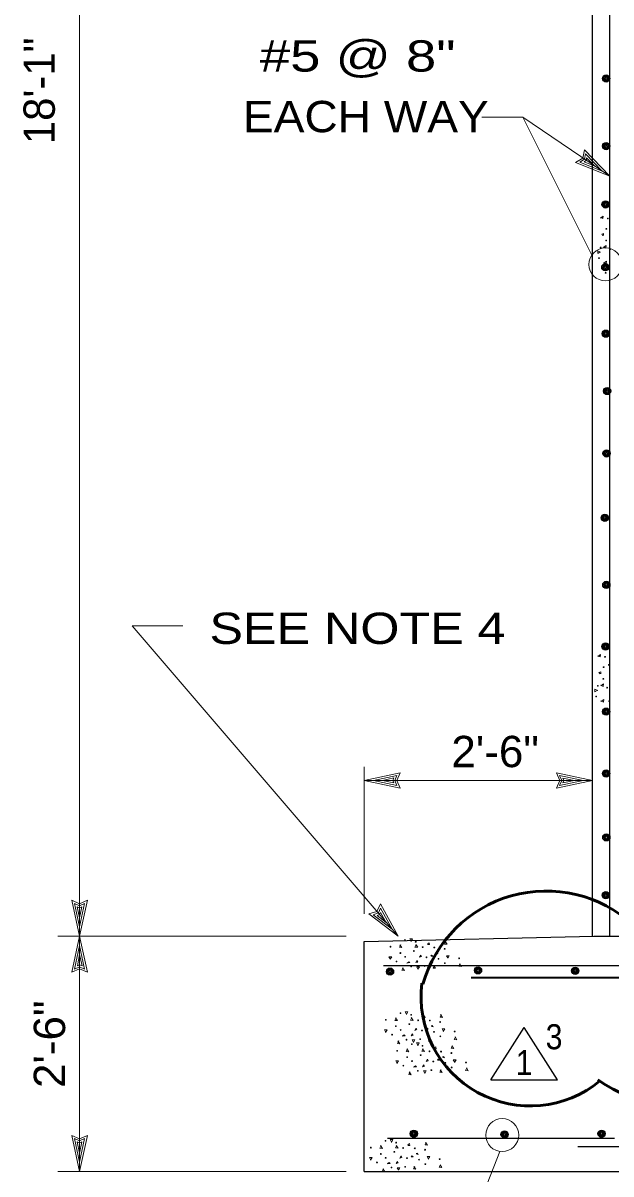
# Model space of a CAD drawing. Extents: x -28.1 to 13.9, y -16.1 to 13.9.
# Drawn here: x -11.031 to -8.685, y 2.985 to 7.58 of the extents above; entities that cross this region are included whole.
import ezdxf
from ezdxf.enums import TextEntityAlignment as Align

# ---------------------------------------------------------------- set-up
doc = ezdxf.new("R2010")
doc.units = 0
doc.header["$LTSCALE"] = 0.05
doc.layers.add('1', color=7, linetype='Continuous', lineweight=13)
doc.layers.add('2', color=7, linetype='Continuous', lineweight=13)

msp = doc.modelspace()

# ---------------------------------------------------------------- linework, layer by layer
at = {"layer": '1'}
for p, q in [((-10.80504, 3.93369), (-10.80504, 10.50069)), ((-9.03704, 7.20369), (-8.76104, 6.65269)), ((-8.80904, 7.02469), (-8.79004, 7.03569)), ((-8.79204, 7.02569), (-8.78304, 7.03169)), ((-8.68904, 6.96769), (-8.79104, 7.07369)), ((-8.79004, 7.03569), (-8.78604, 7.05769)), ((-8.72004, 6.98869), (-8.78604, 7.05769)), ((-8.78304, 7.03169), (-8.78204, 7.04169)), ((-8.74904, 7.00869), (-8.78204, 7.04169)), ((-8.68904, 6.96769), (-8.82604, 7.02269)), ((-8.72004, 6.98869), (-8.80904, 7.02469)), ((-8.74904, 7.00869), (-8.79204, 7.02569)), ((-9.67004, 4.02269), (-9.67004, 4.60969)), ((-9.67004, 4.55569), (-9.52604, 4.58669)), ((-9.67004, 4.55569), (-8.75904, 4.55569)), ((-9.67004, 4.55569), (-9.52604, 4.52469)), ((-9.63304, 4.55569), (-9.53904, 4.57569)), ((-9.63304, 4.55569), (-9.53904, 4.53569)), ((-9.59704, 4.55569), (-9.55204, 4.56569)), ((-9.59704, 4.55569), (-9.55204, 4.54669)), ((-9.55204, 4.56569), (-9.55604, 4.55569)), ((-9.55604, 4.55569), (-9.55204, 4.54669)), ((-9.53904, 4.57569), (-9.54804, 4.55569)), ((-9.54804, 4.55569), (-9.53904, 4.53569)), ((-8.75904, 4.55569), (-8.90304, 4.58669)), ((-8.75904, 4.55569), (-8.90304, 4.52469)), ((-8.79604, 4.55569), (-8.89004, 4.57569)), ((-8.88104, 4.55569), (-8.89004, 4.57569)), ((-8.79604, 4.55569), (-8.89004, 4.53569)), ((-8.89004, 4.53569), (-8.88104, 4.55569)), ((-8.83204, 4.55569), (-8.87704, 4.56469)), ((-8.87304, 4.55569), (-8.87704, 4.56469)), ((-8.83204, 4.55569), (-8.87704, 4.54569)), ((-8.87704, 4.54569), (-8.87304, 4.55569)), ((-10.80504, 3.93369), (-10.83604, 4.07769)), ((-10.80504, 3.97069), (-10.82504, 4.06469)), ((-10.82504, 4.06469), (-10.80504, 4.05569)), ((-10.80504, 4.00669), (-10.81504, 4.05169)), ((-10.81504, 4.05169), (-10.80504, 4.04769)), ((-10.80504, 3.93369), (-10.77404, 4.07769)), ((-10.80504, 3.97069), (-10.78504, 4.06469)), ((-10.80504, 4.05569), (-10.78504, 4.06469)), ((-10.80504, 4.00669), (-10.79604, 4.05169)), ((-10.80504, 4.04769), (-10.79604, 4.05169)), ((-9.61304, 4.02669), (-9.60404, 4.04569)), ((-9.53404, 3.93369), (-9.60404, 4.06369)), ((-9.55804, 3.96169), (-9.60404, 4.04569)), ((-9.53404, 3.93369), (-9.65104, 4.02269)), ((-9.63404, 4.01969), (-9.61304, 4.02669)), ((-9.55804, 3.96169), (-9.63404, 4.01969)), ((-9.61804, 4.01669), (-9.60804, 4.02069)), ((-9.58204, 3.98869), (-9.61804, 4.01669)), ((-9.60804, 4.02069), (-9.60404, 4.02869)), ((-9.58204, 3.98869), (-9.60404, 4.02869)), ((-9.74204, 3.93369), (-10.89204, 3.93369)), ((-10.80504, 3.93369), (-10.83604, 3.78969)), ((-10.80504, 2.99469), (-10.80504, 3.93369)), ((-10.80504, 3.93369), (-10.77404, 3.78969)), ((-10.80504, 3.89669), (-10.82504, 3.80269)), ((-10.80504, 3.86069), (-10.81404, 3.81569)), ((-10.80504, 3.89669), (-10.78504, 3.80269)), ((-10.80504, 3.86069), (-10.79504, 3.81569)), ((-10.80504, 3.81969), (-10.81404, 3.81569)), ((-10.79504, 3.81569), (-10.80504, 3.81969)), ((-10.80504, 3.81169), (-10.82504, 3.80269)), ((-10.78504, 3.80269), (-10.80504, 3.81169)), ((-10.80504, 2.99469), (-10.83604, 3.13869)), ((-10.80504, 3.03169), (-10.82504, 3.12569)), ((-10.82504, 3.12569), (-10.80504, 3.11669)), ((-10.80504, 2.99469), (-10.77404, 3.13869)), ((-10.80504, 3.03169), (-10.78504, 3.12569)), ((-10.80504, 3.11669), (-10.78504, 3.12569)), ((-10.80504, 3.06769), (-10.81504, 3.11269)), ((-10.81504, 3.11269), (-10.80504, 3.10869)), ((-10.80504, 3.06769), (-10.79604, 3.11269)), ((-10.80504, 3.10869), (-10.79604, 3.11269)), ((-9.26904, 2.71669), (-9.12904, 3.07469)), ((-9.74204, 2.99469), (-10.89204, 2.99469))]:
    msp.add_line(p, q, dxfattribs=at)
at = {"layer": '1', "lineweight": 25}
for p, q in [((-8.75904, 3.93369), (-8.75904, 10.50069)), ((-8.68904, 3.93369), (-8.68904, 10.45869)), ((-9.67004, 2.99469), (-9.67004, 3.91269)), ((-9.59204, 3.81669), (-8.42904, 3.81669)), ((-9.16442, 3.3604), (-9.03142, 3.5694)), ((-8.89842, 3.3604), (-9.03142, 3.5694)), ((-9.16442, 3.3604), (-8.89842, 3.3604)), ((-9.57604, 3.12769), (-8.67104, 3.12769)), ((-8.81704, 3.09369), (-8.50904, 3.09369)), ((-9.67004, 2.99469), (-8.17604, 2.99469))]:
    msp.add_line(p, q, dxfattribs=at)
at = {"layer": '1', "lineweight": 35}
msp.add_line((-9.24232, 3.76845), (-8.0669, 3.76845), dxfattribs=at)
at = {"layer": '1'}
for points in [[(-9.20004, 7.20369), (-9.03704, 7.20369), (-8.68904, 6.96769)], [(-8.82604, 7.02269), (-8.79704, 7.04069), (-8.79104, 7.07369)], [(-9.53404, 3.93369), (-10.59604, 5.17269), (-10.39304, 5.17269)], [(-9.52604, 4.58669), (-9.54004, 4.55569), (-9.52604, 4.52469)], [(-8.90304, 4.52469), (-8.88904, 4.55569), (-8.90304, 4.58669)], [(-10.83604, 4.07769), (-10.80504, 4.06369), (-10.77404, 4.07769)], [(-9.65104, 4.02269), (-9.61904, 4.03269), (-9.60404, 4.06369)], [(-10.77404, 3.78969), (-10.80504, 3.80369), (-10.83604, 3.78969)], [(-10.83604, 3.13869), (-10.80504, 3.12469), (-10.77404, 3.13869)]]:
    msp.add_lwpolyline(points, dxfattribs=at)
at = {"layer": '1', "lineweight": 25}
msp.add_lwpolyline([(-9.67004, 3.91269), (-8.75304, 3.93369), (-8.62604, 3.93369)], dxfattribs=at)
for centre, radius in [((-8.70457, 7.35841), 0.01445), ((-8.70457, 7.35841), 0.01121), ((-8.70457, 7.35841), 0.00822), ((-8.70457, 7.35841), 0.00415), ((-8.70457, 7.08841), 0.01445), ((-8.70457, 7.08841), 0.01121), ((-8.70457, 7.08841), 0.00822), ((-8.70457, 7.08841), 0.00415), ((-8.70657, 6.85541), 0.01445), ((-8.70657, 6.85541), 0.01121), ((-8.70657, 6.85541), 0.00822), ((-8.70657, 6.85541), 0.00415), ((-8.70757, 6.60441), 0.01445), ((-8.70757, 6.60441), 0.01121), ((-8.70757, 6.60441), 0.00822), ((-8.70757, 6.60441), 0.00415), ((-8.70557, 6.33941), 0.01445), ((-8.70557, 6.33941), 0.01121), ((-8.70557, 6.33941), 0.00822), ((-8.70557, 6.33941), 0.00415), ((-8.70057, 6.11041), 0.01445), ((-8.70057, 6.11041), 0.01121), ((-8.70057, 6.11041), 0.00822), ((-8.70057, 6.11041), 0.00415), ((-8.70257, 5.86141), 0.01445), ((-8.70257, 5.86141), 0.01121), ((-8.70257, 5.86141), 0.00822), ((-8.70257, 5.86141), 0.00415), ((-8.70957, 5.60441), 0.01445), ((-8.70957, 5.60441), 0.01121), ((-8.70957, 5.60441), 0.00822), ((-8.70957, 5.60441), 0.00415), ((-8.70357, 5.33641), 0.01445), ((-8.70357, 5.33641), 0.01121), ((-8.70357, 5.33641), 0.00822), ((-8.70357, 5.33641), 0.00415), ((-8.70657, 5.09041), 0.01445), ((-8.70657, 5.09041), 0.01121), ((-8.70657, 5.09041), 0.00822), ((-8.70657, 5.09041), 0.00415), ((-8.70457, 4.83041), 0.01445), ((-8.70457, 4.83041), 0.01121), ((-8.70457, 4.83041), 0.00822), ((-8.70457, 4.83041), 0.00415), ((-8.70457, 4.58341), 0.01445), ((-8.70457, 4.58341), 0.01121), ((-8.70457, 4.58341), 0.00822), ((-8.70457, 4.58341), 0.00415), ((-8.70357, 4.32841), 0.01445), ((-8.70357, 4.32841), 0.01121), ((-8.70357, 4.32841), 0.00822), ((-8.70357, 4.32841), 0.00415), ((-8.70557, 4.09741), 0.01445), ((-8.70557, 4.09741), 0.01121), ((-8.70557, 4.09741), 0.00822), ((-8.70557, 4.09741), 0.00415), ((-9.56657, 3.79241), 0.01445), ((-9.56657, 3.79241), 0.01121), ((-9.56657, 3.79241), 0.00822), ((-9.56657, 3.79241), 0.00415), ((-9.21557, 3.79741), 0.01445), ((-9.21557, 3.79741), 0.01121), ((-9.21557, 3.79741), 0.00822), ((-9.21557, 3.79741), 0.00415), ((-8.82757, 3.79541), 0.01445), ((-8.82757, 3.79541), 0.01121), ((-8.82757, 3.79541), 0.00822), ((-8.82757, 3.79541), 0.00415), ((-9.47157, 3.14541), 0.01445), ((-9.47157, 3.14541), 0.01121), ((-9.47157, 3.14541), 0.00822), ((-9.47157, 3.14541), 0.00415), ((-9.10957, 3.14241), 0.01445), ((-9.10957, 3.14241), 0.01121), ((-9.10957, 3.14241), 0.00822), ((-9.10957, 3.14241), 0.00415), ((-8.72257, 3.14541), 0.01445), ((-8.72257, 3.14541), 0.01121), ((-8.72257, 3.14541), 0.00822), ((-8.72257, 3.14541), 0.00415)]:
    msp.add_circle(centre, radius, dxfattribs=at)
at = {"layer": '1'}
for centre in [(-8.70704, 6.61569), (-9.11904, 3.13969)]:
    msp.add_circle(centre, 0.0658, dxfattribs=at)
at = {"layer": '1', "lineweight": 53}
for centre, radius, start, end in [((-8.94381, 3.60375), 0.5106, 47.30804, 164.27765), ((-9.00698, 3.69218), 0.43612, 172.84555, 309.56905), ((-8.34111, 3.94628), 0.70763, 235.88932, 325.85163)]:
    msp.add_arc(centre, radius, start, end, dxfattribs=at)
at = {"layer": '2'}
for p, q in [((-8.71704, 6.73069), (-8.72204, 6.73669)), ((-8.72804, 4.98069), (-8.73304, 4.98669)), ((-9.41704, 3.90269), (-9.41104, 3.90769)), ((-9.43504, 3.61069), (-9.42904, 3.61569)), ((-9.39004, 3.48669), (-9.38404, 3.49169)), ((-9.49504, 3.10069), (-9.48904, 3.10569))]:
    msp.add_line(p, q, dxfattribs=at)
for points in [[(-8.72704, 6.80369), (-8.71704, 6.79869), (-8.71604, 6.80869), (-8.72704, 6.80069)], [(-8.72204, 6.73669), (-8.71504, 6.73869), (-8.71504, 6.73069)], [(-8.72904, 6.66469), (-8.73804, 6.65969), (-8.73804, 6.67069), (-8.72704, 6.66469)], [(-8.71504, 6.68569), (-8.70504, 6.68069), (-8.70404, 6.69169), (-8.71504, 6.68369)], [(-8.71404, 6.62369), (-8.70404, 6.61869), (-8.70304, 6.62869), (-8.71404, 6.62069)], [(-8.73804, 5.05369), (-8.72804, 5.04869), (-8.72704, 5.05869), (-8.73804, 5.05069)], [(-8.69304, 5.01369), (-8.69504, 5.01869), (-8.68904, 5.02169), (-8.69204, 5.01369)], [(-8.73304, 4.98669), (-8.72604, 4.98869), (-8.72604, 4.98069)], [(-8.74004, 4.91469), (-8.74904, 4.90969), (-8.74904, 4.92069), (-8.73804, 4.91469)], [(-8.72604, 4.93569), (-8.71604, 4.93069), (-8.71504, 4.94169), (-8.72604, 4.93369)], [(-8.72504, 4.87369), (-8.71504, 4.86869), (-8.71404, 4.87869), (-8.72504, 4.87069)], [(-9.48304, 3.91469), (-9.48804, 3.92369), (-9.47704, 3.92369), (-9.48304, 3.91269)], [(-9.41104, 3.90769), (-9.40904, 3.90069), (-9.41704, 3.90069)], [(-9.34404, 3.91269), (-9.34904, 3.90269), (-9.33904, 3.90169), (-9.34704, 3.91269)], [(-9.52404, 3.89969), (-9.52904, 3.88969), (-9.51904, 3.88869), (-9.52704, 3.89969)], [(-9.46204, 3.90069), (-9.46704, 3.89069), (-9.45604, 3.88969), (-9.46404, 3.90069)], [(-9.38404, 3.86769), (-9.37904, 3.86969), (-9.37604, 3.86369), (-9.38404, 3.86669)], [(-9.56604, 3.84369), (-9.57104, 3.85169), (-9.56004, 3.85169), (-9.56604, 3.84169)], [(-9.49704, 3.82869), (-9.49204, 3.83169), (-9.48804, 3.82869), (-9.50004, 3.82669)], [(-9.40404, 3.85469), (-9.40104, 3.85869), (-9.39604, 3.85469), (-9.40304, 3.85369)], [(-9.39004, 3.81669), (-9.39504, 3.80669), (-9.38504, 3.80569), (-9.39304, 3.81669)], [(-9.33604, 3.84769), (-9.34104, 3.85569), (-9.33004, 3.85569), (-9.33604, 3.84569)], [(-9.28704, 3.82369), (-9.29204, 3.81369), (-9.28204, 3.81269), (-9.28904, 3.82369)], [(-9.51404, 3.80769), (-9.51904, 3.79769), (-9.50904, 3.79669), (-9.51704, 3.80769)], [(-9.45504, 3.80269), (-9.46004, 3.81169), (-9.44904, 3.81169), (-9.45504, 3.80169)], [(-9.50104, 3.62269), (-9.50604, 3.63169), (-9.49504, 3.63169), (-9.50104, 3.62069)], [(-9.54204, 3.60769), (-9.54704, 3.59769), (-9.53704, 3.59669), (-9.54504, 3.60769)], [(-9.48004, 3.60869), (-9.48504, 3.59869), (-9.47404, 3.59769), (-9.48204, 3.60869)], [(-9.42904, 3.61569), (-9.42704, 3.60869), (-9.43504, 3.60869)], [(-9.36204, 3.62069), (-9.36704, 3.61069), (-9.35704, 3.60969), (-9.36504, 3.62069)], [(-9.58404, 3.55169), (-9.58904, 3.55969), (-9.57804, 3.55969), (-9.58404, 3.54969)], [(-9.51504, 3.53669), (-9.51004, 3.53969), (-9.50604, 3.53669), (-9.51804, 3.53469)], [(-9.42204, 3.56269), (-9.41904, 3.56669), (-9.41404, 3.56269), (-9.42104, 3.56169)], [(-9.40204, 3.57569), (-9.39704, 3.57769), (-9.39404, 3.57169), (-9.40204, 3.57469)], [(-9.35404, 3.55569), (-9.35904, 3.56369), (-9.34804, 3.56369), (-9.35404, 3.55369)], [(-9.53204, 3.51569), (-9.53704, 3.50569), (-9.52704, 3.50469), (-9.53504, 3.51569)], [(-9.47304, 3.51069), (-9.47804, 3.51969), (-9.46704, 3.51969), (-9.47304, 3.50969)], [(-9.45604, 3.49869), (-9.46104, 3.50769), (-9.45004, 3.50769), (-9.45604, 3.49669)], [(-9.40804, 3.52469), (-9.41304, 3.51469), (-9.40304, 3.51369), (-9.41104, 3.52469)], [(-9.31704, 3.49669), (-9.32204, 3.48669), (-9.31204, 3.48569), (-9.32004, 3.49669)], [(-9.30504, 3.53169), (-9.31004, 3.52169), (-9.30004, 3.52069), (-9.30704, 3.53169)], [(-9.49704, 3.48369), (-9.50204, 3.47369), (-9.49204, 3.47269), (-9.50004, 3.48369)], [(-9.43504, 3.48469), (-9.44004, 3.47469), (-9.42904, 3.47369), (-9.43704, 3.48469)], [(-9.38404, 3.49169), (-9.38204, 3.48469), (-9.39004, 3.48469)], [(-9.35704, 3.45169), (-9.35204, 3.45369), (-9.34904, 3.44769), (-9.35704, 3.45069)], [(-9.53904, 3.42769), (-9.54404, 3.43569), (-9.53304, 3.43569), (-9.53904, 3.42569)], [(-9.47004, 3.41269), (-9.46504, 3.41569), (-9.46104, 3.41269), (-9.47304, 3.41069)], [(-9.37704, 3.43869), (-9.37404, 3.44269), (-9.36904, 3.43869), (-9.37604, 3.43769)], [(-9.36304, 3.40069), (-9.36804, 3.39069), (-9.35804, 3.38969), (-9.36604, 3.40069)], [(-9.30904, 3.43169), (-9.31404, 3.43969), (-9.30304, 3.43969), (-9.30904, 3.42969)], [(-9.26004, 3.40769), (-9.26504, 3.39769), (-9.25504, 3.39669), (-9.26204, 3.40769)], [(-9.48704, 3.39169), (-9.49204, 3.38169), (-9.48204, 3.38069), (-9.49004, 3.39169)], [(-9.42804, 3.38669), (-9.43304, 3.39569), (-9.42204, 3.39569), (-9.42804, 3.38569)], [(-9.60204, 3.09769), (-9.60704, 3.08769), (-9.59704, 3.08669), (-9.60504, 3.09769)], [(-9.56104, 3.11269), (-9.56604, 3.12169), (-9.55504, 3.12169), (-9.56104, 3.11069)], [(-9.54004, 3.09869), (-9.54504, 3.08869), (-9.53404, 3.08769), (-9.54204, 3.09869)], [(-9.48904, 3.10569), (-9.48704, 3.09869), (-9.49504, 3.09869)], [(-9.42204, 3.11069), (-9.42704, 3.10069), (-9.41704, 3.09969), (-9.42504, 3.11069)], [(-9.64404, 3.04169), (-9.64904, 3.04969), (-9.63804, 3.04969), (-9.64404, 3.03969)], [(-9.48204, 3.05269), (-9.47904, 3.05669), (-9.47404, 3.05269), (-9.48104, 3.05169)], [(-9.46204, 3.06569), (-9.45704, 3.06769), (-9.45404, 3.06169), (-9.46204, 3.06469)], [(-9.41404, 3.04569), (-9.41904, 3.05369), (-9.40804, 3.05369), (-9.41404, 3.04369)], [(-9.59204, 3.00569), (-9.59704, 2.99569), (-9.58704, 2.99469), (-9.59504, 3.00569)], [(-9.57504, 3.02669), (-9.57004, 3.02969), (-9.56604, 3.02669), (-9.57804, 3.02469)], [(-9.53304, 3.00069), (-9.53804, 3.00969), (-9.52704, 3.00969), (-9.53304, 2.99969)], [(-9.46804, 3.01469), (-9.47304, 3.00469), (-9.46304, 3.00369), (-9.47104, 3.01469)], [(-9.36504, 3.02169), (-9.37004, 3.01169), (-9.36004, 3.01069), (-9.36704, 3.02169)]]:
    msp.add_lwpolyline(points, dxfattribs=at)
for points in [[(-9.46404, 3.82869), (-9.45904, 3.83669), (-9.45604, 3.83069)], [(-9.44904, 3.84969), (-9.44404, 3.85869), (-9.44104, 3.85269)], [(-9.48204, 3.53669), (-9.47704, 3.54469), (-9.47404, 3.53869)], [(-9.46704, 3.55769), (-9.46204, 3.56669), (-9.45904, 3.56069)], [(-9.43704, 3.41269), (-9.43204, 3.42069), (-9.42904, 3.41469)], [(-9.42204, 3.43369), (-9.41704, 3.44269), (-9.41404, 3.43669)], [(-9.54204, 3.02669), (-9.53704, 3.03469), (-9.53404, 3.02869)], [(-9.52704, 3.04769), (-9.52204, 3.05669), (-9.51904, 3.05069)]]:
    msp.add_lwpolyline(points, close=True, dxfattribs=at)
for centre in [(-8.70342, 6.75769), (-8.69767, 6.79894), (-8.70442, 6.71144), (-8.72617, 6.68369), (-8.68917, 6.67619), (-8.73292, 6.64094), (-8.70617, 6.58269), (-8.71442, 5.00769), (-8.70867, 5.04894), (-8.71542, 4.96144), (-8.73717, 4.93369), (-8.70017, 4.92619), (-8.74392, 4.89094), (-8.69192, 4.87244), (-8.71717, 4.83269), (-9.50679, 3.91856), (-9.46404, 3.91181), (-9.56504, 3.89181), (-9.52529, 3.86656), (-9.47154, 3.87481), (-9.43629, 3.89006), (-9.39004, 3.88906), (-9.34879, 3.88331), (-9.54054, 3.83281), (-9.50604, 3.85131), (-9.48254, 3.81256), (-9.42854, 3.81506), (-9.42104, 3.84956), (-9.37304, 3.84381), (-9.34779, 3.82606), (-9.29054, 3.84556), (-9.58304, 3.59981), (-9.52479, 3.62656), (-9.48954, 3.58281), (-9.48204, 3.61981), (-9.45429, 3.59806), (-9.40804, 3.59706), (-9.36679, 3.59131), (-9.55854, 3.54081), (-9.54329, 3.57456), (-9.52404, 3.55931), (-9.43904, 3.55756), (-9.39104, 3.55181), (-9.30854, 3.55356), (-9.50054, 3.52056), (-9.47979, 3.50256), (-9.44654, 3.52306), (-9.43704, 3.49581), (-9.36579, 3.53406), (-9.53804, 3.47581), (-9.49829, 3.45056), (-9.44454, 3.45881), (-9.40929, 3.47406), (-9.36304, 3.47306), (-9.32179, 3.46731), (-9.51354, 3.41681), (-9.47904, 3.43531), (-9.40154, 3.39906), (-9.39404, 3.43356), (-9.34604, 3.42781), (-9.32079, 3.41006), (-9.26354, 3.42956), (-9.45554, 3.39656), (-9.64304, 3.08981), (-9.58479, 3.11656), (-9.54204, 3.10981), (-9.51429, 3.08806), (-9.46804, 3.08706), (-9.42679, 3.08131), (-9.60329, 3.06456), (-9.58404, 3.04931), (-9.54954, 3.07281), (-9.49904, 3.04756), (-9.45104, 3.04181), (-9.36854, 3.04356), (-9.61854, 3.03081), (-9.56054, 3.01056), (-9.50654, 3.01306), (-9.42579, 3.02406)]:
    msp.add_circle(centre, 0.00162, dxfattribs=at)

# ---------------------------------------------------------------- texts
at = {"layer": '1'}
msp.add_text('18\'-1"', height=0.125, rotation=90, dxfattribs=at).set_placement((-10.90404, 7.3089), align=Align.CENTER)
for s, width, p in [('#5 @ 8"', 1.3, (-10.08604, 7.38569)), ('SEE NOTE 4', 1.2, (-10.28704, 5.10069))]:
    msp.add_text(s, height=0.125, dxfattribs=dict(at, width=width)).set_placement(p)
for s, height, width, p in [('EACH WAY', 0.125, 1.1, (-9.66303, 7.14369)), ('2\'-6"', 0.125, 1.05, (-9.14716, 4.60869)), ('3', 0.1, 0.9, (-8.91208, 3.4824)), ('1', 0.1, 0.9, (-9.03108, 3.3794))]:
    msp.add_text(s, height=height, dxfattribs=dict(at, width=width)).set_placement(p, align=Align.CENTER)
at = {"layer": '1', "width": 1.05}
msp.add_text('2\'-6"', height=0.125, rotation=90, dxfattribs=at).set_placement((-10.86304, 3.50257), align=Align.CENTER)

doc.saveas('drawing.dxf')
